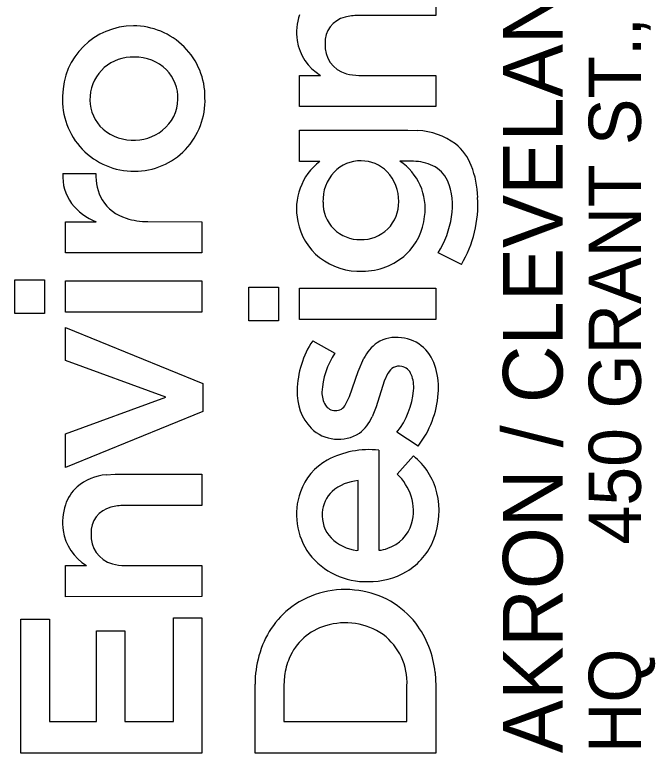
# Model space of a CAD drawing. Extents: x 0 to 1700, y 0 to 1100.
# Drawn here: x 1618.85 to 1649.43, y 131.9 to 167.17 of the extents above; entities that cross this region are included whole.
import ezdxf

# ---------------------------------------------------------------- set-up
doc = ezdxf.new("R2010")
doc.units = 0
doc.layers.add('SH_Data', color=7, linetype='Continuous')

msp = doc.modelspace()

# ---------------------------------------------------------------- linework, layer by layer
at = {"layer": 'SH_Data'}
for p, q in [((1638.958, 168.633), (1638.958, 167.144)), ((1638.958, 167.144), (1635.242, 167.14)), ((1632.444, 164.275), (1633.449, 164.277)), ((1632.444, 162.785), (1632.444, 164.275)), ((1635.284, 164.277), (1638.957, 164.277)), ((1638.957, 164.277), (1638.958, 162.789)), ((1638.958, 162.789), (1632.444, 162.785)), ((1632.445, 160.168), (1632.445, 161.661)), ((1632.445, 161.661), (1637.618, 161.661)), ((1637.618, 161.661), (1638.096, 161.643)), ((1633.418, 160.168), (1632.445, 160.168)), ((1637.881, 160.178), (1637.243, 160.181)), ((1621.149, 159.597), (1622.727, 159.597)), ((1621.271, 155.797), (1621.271, 157.289)), ((1621.271, 157.289), (1622.736, 157.289)), ((1625.206, 157.29), (1627.786, 157.287)), ((1627.786, 157.287), (1627.782, 155.797)), ((1627.782, 155.797), (1621.271, 155.797)), ((1640.18, 155.245), (1639.06, 155.799)), ((1618.853, 152.909), (1618.853, 154.513)), ((1618.853, 154.513), (1620.272, 154.513)), ((1620.272, 154.513), (1620.272, 152.909)), ((1621.271, 152.971), (1621.271, 154.464)), ((1621.271, 154.464), (1627.786, 154.464)), ((1627.786, 154.464), (1627.786, 152.971)), ((1630.025, 152.555), (1630.025, 154.159)), ((1630.025, 154.159), (1631.444, 154.159)), ((1631.444, 154.159), (1631.444, 152.555)), ((1632.444, 152.617), (1632.444, 154.11)), ((1632.444, 154.11), (1638.958, 154.11)), ((1638.958, 154.11), (1638.958, 152.617)), ((1620.272, 152.909), (1618.853, 152.909)), ((1627.786, 152.971), (1621.271, 152.971)), ((1631.444, 152.555), (1630.025, 152.555)), ((1638.958, 152.617), (1632.444, 152.617)), ((1621.271, 150.663), (1621.271, 152.23)), ((1621.271, 152.23), (1627.835, 149.565)), ((1633.076, 151.603), (1634.134, 151.013)), ((1626.058, 148.899), (1621.271, 150.663)), ((1635.242, 150.129), (1635.518, 150.763)), ((1634.837, 148.934), (1635.242, 150.129)), ((1636.671, 150.05), (1636.492, 149.665)), ((1636.492, 149.665), (1636.106, 148.441)), ((1627.835, 149.565), (1627.835, 148.22)), ((1621.271, 147.147), (1626.058, 148.899)), ((1634.649, 148.558), (1634.837, 148.934)), ((1627.835, 148.22), (1621.271, 145.543)), ((1636.106, 148.441), (1635.911, 147.96)), ((1621.271, 145.543), (1621.271, 147.147)), ((1638.107, 146.571), (1637.099, 147.235)), ((1636.226, 146.373), (1636.232, 141.597)), ((1637.114, 145.232), (1637.884, 146.1)), ((1623.219, 145.199), (1623.645, 145.222)), ((1623.645, 145.222), (1627.785, 145.222)), ((1627.785, 145.222), (1627.786, 143.732)), ((1635.245, 141.591), (1635.245, 144.917)), ((1627.786, 143.732), (1624.07, 143.729)), ((1635.18, 141.583), (1635.245, 141.591)), ((1621.271, 140.864), (1622.276, 140.866)), ((1621.271, 139.373), (1621.271, 140.864)), ((1624.111, 140.866), (1627.785, 140.866)), ((1627.785, 140.866), (1627.786, 139.378)), ((1627.786, 139.378), (1621.271, 139.373)), ((1619.149, 131.896), (1619.149, 138.299)), ((1619.149, 138.299), (1620.506, 138.299)), ((1620.506, 138.299), (1620.506, 133.413)), ((1626.428, 133.413), (1626.428, 138.361)), ((1626.428, 138.361), (1627.786, 138.361)), ((1627.786, 138.361), (1627.786, 131.896)), ((1622.752, 133.413), (1622.752, 137.744)), ((1622.752, 137.744), (1624.109, 137.744)), ((1624.109, 137.744), (1624.109, 133.413)), ((1631.733, 135.589), (1631.703, 135.115)), ((1638.924, 135.748), (1638.958, 135.105)), ((1630.322, 131.899), (1630.322, 135.2)), ((1631.703, 135.115), (1631.703, 133.419)), ((1637.575, 133.417), (1637.576, 135.12)), ((1638.958, 135.105), (1638.958, 131.9)), ((1620.506, 133.413), (1622.752, 133.413)), ((1624.109, 133.413), (1626.428, 133.413)), ((1631.703, 133.419), (1637.575, 133.417)), ((1627.786, 131.896), (1619.149, 131.896)), ((1638.958, 131.9), (1630.322, 131.899))]:
    msp.add_line(p, q, dxfattribs=at)
for points in [[(1634.392, 168.61), (1634.817, 168.633), (1638.958, 168.633), (1638.958, 167.144), (1635.242, 167.14)], [(1632.444, 162.785), (1632.444, 164.275), (1633.449, 164.277)], [(1635.284, 164.277), (1638.957, 164.277), (1638.958, 162.789), (1632.444, 162.785)], [(1633.418, 160.168), (1632.445, 160.168), (1632.445, 161.661), (1637.618, 161.661), (1638.096, 161.643)], [(1637.881, 160.178), (1637.243, 160.181)], [(1621.149, 159.597), (1622.727, 159.597)], [(1625.206, 157.29), (1627.786, 157.287), (1627.782, 155.797), (1621.271, 155.797)], [(1621.271, 155.797), (1621.271, 157.289), (1622.736, 157.289)], [(1640.18, 155.245), (1639.06, 155.799)], [(1633.076, 151.603), (1634.134, 151.013)], [(1634.649, 148.558), (1634.837, 148.934), (1635.242, 150.129), (1635.518, 150.763)], [(1636.671, 150.05), (1636.492, 149.665), (1636.106, 148.441), (1635.911, 147.96)], [(1638.107, 146.571), (1637.099, 147.235)], [(1636.226, 146.373), (1636.232, 141.597)], [(1637.114, 145.232), (1637.884, 146.1)], [(1623.219, 145.199), (1623.645, 145.222), (1627.785, 145.222), (1627.786, 143.732), (1624.07, 143.729)], [(1635.18, 141.583), (1635.245, 141.591), (1635.245, 144.917)], [(1621.271, 139.373), (1621.271, 140.864), (1622.276, 140.866)], [(1624.111, 140.866), (1627.785, 140.866), (1627.786, 139.378), (1621.271, 139.373)], [(1638.924, 135.748), (1638.958, 135.105), (1638.958, 131.9), (1630.322, 131.899)], [(1631.733, 135.589), (1631.703, 135.115), (1631.703, 133.419), (1637.575, 133.417), (1637.576, 135.12)], [(1630.322, 131.899), (1630.322, 135.2)]]:
    msp.add_lwpolyline(points, dxfattribs=at)
for points in [[(1618.853, 152.909), (1618.853, 154.513), (1620.272, 154.513), (1620.272, 152.909)], [(1621.271, 152.971), (1621.271, 154.464), (1627.786, 154.464), (1627.786, 152.971)], [(1630.025, 152.555), (1630.025, 154.159), (1631.444, 154.159), (1631.444, 152.555)], [(1632.444, 152.617), (1632.444, 154.11), (1638.958, 154.11), (1638.958, 152.617)], [(1621.271, 145.543), (1621.271, 147.147), (1626.058, 148.899), (1621.271, 150.663), (1621.271, 152.23), (1627.835, 149.565), (1627.835, 148.22)], [(1619.149, 131.896), (1619.149, 138.299), (1620.506, 138.299), (1620.506, 133.413), (1622.752, 133.413), (1622.752, 137.744), (1624.109, 137.744), (1624.109, 133.413), (1626.428, 133.413), (1626.428, 138.361), (1627.786, 138.361), (1627.786, 131.896)]]:
    msp.add_lwpolyline(points, close=True, dxfattribs=at)
for centre, radius, start, end in [((1635.109, 166.321), 2.801, 162.274, 187.7917), ((1635.109, 166.321), 2.801, 162.274, 187.7917), ((1634.914, 165.845), 1.249, 103.6868, 182.214), ((1634.914, 165.845), 1.249, 103.6868, 182.214), ((1635.227, 164.84), 2.3, 89.6051, 105.3303), ((1635.227, 164.84), 2.3, 89.6051, 105.3303), ((1624.507, 163.271), 3.37, 89.8476, 179.6405), ((1624.507, 163.271), 3.37, 89.8476, 179.6405), ((1624.529, 163.237), 3.405, 359.5401, 90.2114), ((1624.529, 163.237), 3.405, 359.5401, 90.2114), ((1634.686, 166.312), 2.381, 188.9646, 238.6987), ((1634.686, 166.312), 2.381, 188.9646, 238.6987), ((1635.04, 165.69), 1.378, 175.5844, 255.1382), ((1635.04, 165.69), 1.378, 175.5844, 255.1382), ((1624.461, 163.132), 2.02, 87.0481, 175.5726), ((1624.461, 163.132), 2.02, 87.0481, 175.5726), ((1624.602, 163), 2.149, 45.8426, 90.9801), ((1624.602, 163), 2.149, 45.8426, 90.9801), ((1624.729, 163.211), 1.911, 357.8857, 44.159), ((1624.729, 163.211), 1.911, 357.8857, 44.159), ((1635.264, 166.385), 2.107, 254.0891, 270.5284), ((1635.264, 166.385), 2.107, 254.0891, 270.5284), ((1624.541, 163.104), 3.409, 176.8344, 270.4038), ((1624.541, 163.104), 3.409, 176.8344, 270.4038), ((1624.365, 163.125), 1.924, 175.1538, 221.1471), ((1624.365, 163.125), 1.924, 175.1538, 221.1471), ((1624.562, 163.069), 3.374, 270.0624, 2.3776), ((1624.562, 163.069), 3.374, 270.0624, 2.3776), ((1624.723, 163.159), 1.915, 308.2894, 359.4347), ((1624.723, 163.159), 1.915, 308.2894, 359.4347), ((1624.459, 163.303), 2.114, 223.0999, 268.8089), ((1624.459, 163.303), 2.114, 223.0999, 268.8089), ((1624.548, 163.395), 2.209, 266.5651, 308.0608), ((1624.548, 163.395), 2.209, 266.5651, 308.0608), ((1637.953, 158.394), 3.251, 53.4034, 87.4906), ((1637.953, 158.394), 3.251, 53.4034, 87.4906), ((1638.259, 159.02), 2.571, 21.6075, 50.5577), ((1638.259, 159.02), 2.571, 21.6075, 50.5577), ((1635.146, 157.906), 2.846, 127.3748, 192.2247), ((1635.146, 157.906), 2.846, 127.3748, 192.2247), ((1635.347, 158.464), 1.73, 88.473, 136.4256), ((1635.347, 158.464), 1.73, 88.473, 136.4256), ((1635.407, 158.481), 1.712, 44.2719, 90.4762), ((1635.407, 158.481), 1.712, 44.2719, 90.4762), ((1635.71, 157.914), 2.736, 352.1125, 55.923), ((1635.71, 157.914), 2.736, 352.1125, 55.923), ((1637.833, 157.862), 2.316, 65.0169, 88.8011), ((1637.833, 157.862), 2.316, 65.0169, 88.8011), ((1638.13, 158.578), 1.543, 26.2681, 63.803), ((1638.13, 158.578), 1.543, 26.2681, 63.803), ((1636.535, 158.357), 4.418, 1.1514, 21.3627), ((1636.535, 158.357), 4.418, 1.1514, 21.3627), ((1623.308, 159.441), 2.164, 175.8731, 216.3475), ((1623.308, 159.441), 2.164, 175.8731, 216.3475), ((1625.043, 159.474), 2.32, 176.9688, 209.6064), ((1625.043, 159.474), 2.32, 176.9688, 209.6064), ((1635.571, 158.301), 2.005, 137.4674, 182.3324), ((1635.571, 158.301), 2.005, 137.4674, 182.3324), ((1635.184, 158.3), 1.998, 358.5714, 43.5376), ((1635.184, 158.3), 1.998, 358.5714, 43.5376), ((1636.783, 158.077), 2.976, 349.3073, 23.4307), ((1636.783, 158.077), 2.976, 349.3073, 23.4307), ((1635.269, 158.122), 5.692, 329.6388, 3.26), ((1635.269, 158.122), 5.692, 329.6388, 3.26), ((1623.733, 159.858), 2.755, 218.0981, 248.7907), ((1623.733, 159.858), 2.755, 218.0981, 248.7907), ((1624.757, 159.407), 2.039, 211.9447, 253.2028), ((1624.757, 159.407), 2.039, 211.9447, 253.2028), ((1635.323, 158.185), 1.755, 178.8821, 271.0837), ((1635.323, 158.185), 1.755, 178.8821, 271.0837), ((1635.409, 158.202), 1.773, 268.2788, 1.5502), ((1635.409, 158.202), 1.773, 268.2788, 1.5502), ((1625.233, 160.825), 3.535, 252.4655, 269.573), ((1625.233, 160.825), 3.535, 252.4655, 269.573), ((1635.494, 157.854), 2.944, 313.742, 353.8554), ((1635.494, 157.854), 2.944, 313.742, 353.8554), ((1635.369, 158.167), 4.385, 327.3149, 351.5748), ((1635.369, 158.167), 4.385, 327.3149, 351.5748), ((1635.232, 157.848), 2.919, 190.7518, 231.2892), ((1635.232, 157.848), 2.919, 190.7518, 231.2892), ((1635.477, 157.951), 3.026, 269.6361, 312.7088), ((1635.477, 157.951), 3.026, 269.6361, 312.7088), ((1635.316, 158.056), 3.134, 232.4606, 272.5902), ((1635.316, 158.056), 3.134, 232.4606, 272.5902), ((1637.03, 150.13), 1.632, 80.1719, 122.5197), ((1637.03, 150.13), 1.632, 80.1719, 122.5197), ((1637.139, 149.912), 1.834, 47.7934, 84.6892), ((1637.139, 149.912), 1.834, 47.7934, 84.6892), ((1636.818, 149.129), 4.486, 146.531, 178.7571), ((1636.818, 149.129), 4.486, 146.531, 178.7571), ((1637.33, 149.856), 2.026, 125.5118, 153.4159), ((1637.33, 149.856), 2.026, 125.5118, 153.4159), ((1637.259, 148.945), 3.747, 146.5112, 176.9101), ((1637.259, 148.945), 3.747, 146.5112, 176.9101), ((1636.894, 149.73), 2.134, 14.9966, 46.2063), ((1636.894, 149.73), 2.134, 14.9966, 46.2063), ((1637.192, 149.815), 0.571, 76.6609, 155.7053), ((1637.192, 149.815), 0.571, 76.6609, 155.7053), ((1637.199, 149.756), 0.628, 21.5098, 78.5262), ((1637.199, 149.756), 0.628, 21.5098, 78.5262), ((1636.296, 149.383), 1.605, 354.5726, 22.068), ((1636.296, 149.383), 1.605, 354.5726, 22.068), ((1635.522, 149.337), 3.561, 355.8306, 15.3914), ((1635.522, 149.337), 3.561, 355.8306, 15.3914), ((1634.833, 149.119), 2.503, 177.5366, 222.7932), ((1634.833, 149.119), 2.503, 177.5366, 222.7932), ((1634.124, 149.575), 3.785, 321.811, 354.7969), ((1634.124, 149.575), 3.785, 321.811, 354.7969), ((1634.655, 149.117), 1.138, 178.4747, 211.0868), ((1634.655, 149.117), 1.138, 178.4747, 211.0868), ((1634.476, 149.41), 4.609, 321.9777, 355.8738), ((1634.476, 149.41), 4.609, 321.9777, 355.8738), ((1634.166, 148.835), 0.574, 212.2368, 268.3777), ((1634.166, 148.835), 0.574, 212.2368, 268.3777), ((1634.171, 148.795), 0.534, 267.716, 333.7337), ((1634.171, 148.795), 0.534, 267.716, 333.7337), ((1634.049, 148.79), 2.039, 308.0877, 335.9874), ((1634.049, 148.79), 2.039, 308.0877, 335.9874), ((1634.3, 148.767), 1.875, 225.9854, 302.4797), ((1634.3, 148.767), 1.875, 225.9854, 302.4797), ((1635.76, 142.207), 4.192, 83.615, 118.2876), ((1635.76, 142.207), 4.192, 83.615, 118.2876), ((1635.872, 143.584), 3.222, 13.5336, 51.3615), ((1635.872, 143.584), 3.222, 13.5336, 51.3615), ((1635.12, 143.453), 2.792, 118.8308, 160.6244), ((1635.12, 143.453), 2.792, 118.8308, 160.6244), ((1623.435, 142.714), 2.494, 94.9696, 130.2225), ((1623.435, 142.714), 2.494, 94.9696, 130.2225), ((1635.189, 143.278), 2.743, 19.0357, 45.4406), ((1635.189, 143.278), 2.743, 19.0357, 45.4406), ((1635.393, 142.805), 2.118, 94.008, 130.8817), ((1635.393, 142.805), 2.118, 94.008, 130.8817), ((1623.174, 143.131), 2.008, 132.2219, 161.6818), ((1623.174, 143.131), 2.008, 132.2219, 161.6818), ((1635.521, 143.306), 3.219, 160.5201, 215.7831), ((1635.521, 143.306), 3.219, 160.5201, 215.7831), ((1635.024, 143.314), 1.492, 132.9851, 177.179), ((1635.024, 143.314), 1.492, 132.9851, 177.179), ((1635.318, 143.461), 3.79, 339.3542, 13.3785), ((1635.318, 143.461), 3.79, 339.3542, 13.3785), ((1635.535, 143.485), 2.35, 344.6059, 17.007), ((1635.535, 143.485), 2.35, 344.6059, 17.007), ((1623.936, 142.91), 2.801, 162.2736, 187.7919), ((1623.936, 142.91), 2.801, 162.2736, 187.7919), ((1623.741, 142.433), 1.249, 103.6865, 182.2187), ((1623.741, 142.433), 1.249, 103.6865, 182.2187), ((1624.054, 141.428), 2.301, 89.6049, 105.3284), ((1624.054, 141.428), 2.301, 89.6049, 105.3284), ((1635.085, 143.252), 1.557, 175.0013, 223.283), ((1635.085, 143.252), 1.557, 175.0013, 223.283), ((1623.513, 142.901), 2.381, 188.962, 238.7037), ((1623.513, 142.901), 2.381, 188.962, 238.7037), ((1636.12, 143.357), 1.752, 288.0077, 343.5508), ((1636.12, 143.357), 1.752, 288.0077, 343.5508), ((1623.867, 142.279), 1.378, 175.5854, 255.1439), ((1623.867, 142.279), 1.378, 175.5854, 255.1439), ((1635.446, 143.682), 2.116, 225.0619, 262.7974), ((1635.446, 143.682), 2.116, 225.0619, 262.7974), ((1635.947, 143.26), 3.13, 300.9427, 338.7323), ((1635.947, 143.26), 3.13, 300.9427, 338.7323), ((1636.237, 142.608), 1.01, 269.7003, 294.8711), ((1636.237, 142.608), 1.01, 269.7003, 294.8711), ((1635.626, 143.527), 3.436, 217.7452, 271.6543), ((1635.626, 143.527), 3.436, 217.7452, 271.6543), ((1624.092, 142.974), 2.108, 254.0916, 270.5284), ((1624.092, 142.974), 2.108, 254.0916, 270.5284), ((1635.775, 143.62), 3.528, 269.2048, 300.3341), ((1635.775, 143.62), 3.528, 269.2048, 300.3341), ((1634.614, 135.396), 4.321, 81.194, 125.9984), ((1634.614, 135.396), 4.321, 81.194, 125.9984), ((1634.729, 135.566), 4.136, 37.8521, 82.402), ((1634.729, 135.566), 4.136, 37.8521, 82.402), ((1634.693, 135.446), 4.327, 127.2362, 165.148), ((1634.693, 135.446), 4.327, 127.2362, 165.148), ((1634.447, 135.391), 2.699, 106.1881, 157.3861), ((1634.447, 135.391), 2.699, 106.1881, 157.3861), ((1634.639, 134.931), 3.195, 55.6727, 107.2093), ((1634.639, 134.931), 3.195, 55.6727, 107.2093), ((1634.293, 135.283), 4.654, 5.7333, 37.304), ((1634.293, 135.283), 4.654, 5.7333, 37.304), ((1634.646, 135.249), 2.934, 357.4662, 52.2665), ((1634.646, 135.249), 2.934, 357.4662, 52.2665), ((1635.713, 135.141), 5.391, 164.7861, 179.3704), ((1635.713, 135.141), 5.391, 164.7861, 179.3704), ((1634.914, 135.194), 3.206, 157.3571, 172.9275), ((1634.914, 135.194), 3.206, 157.3571, 172.9275)]:
    msp.add_arc(centre, radius, start, end, dxfattribs=at)

# ---------------------------------------------------------------- texts
for s, height, p in [('450 GRANT ST., AKRON, OH  44311', 2.49231, (1648.744, 141.869)), ('AKRON / CLEVELAND / COLUMBUS', 2.84845, (1645.006, 131.9)), ('HQ ', 2.4923, (1648.744, 131.9))]:
    msp.add_text(s, height=height, rotation=90, dxfattribs=at).set_placement(p)

doc.saveas('drawing.dxf')
